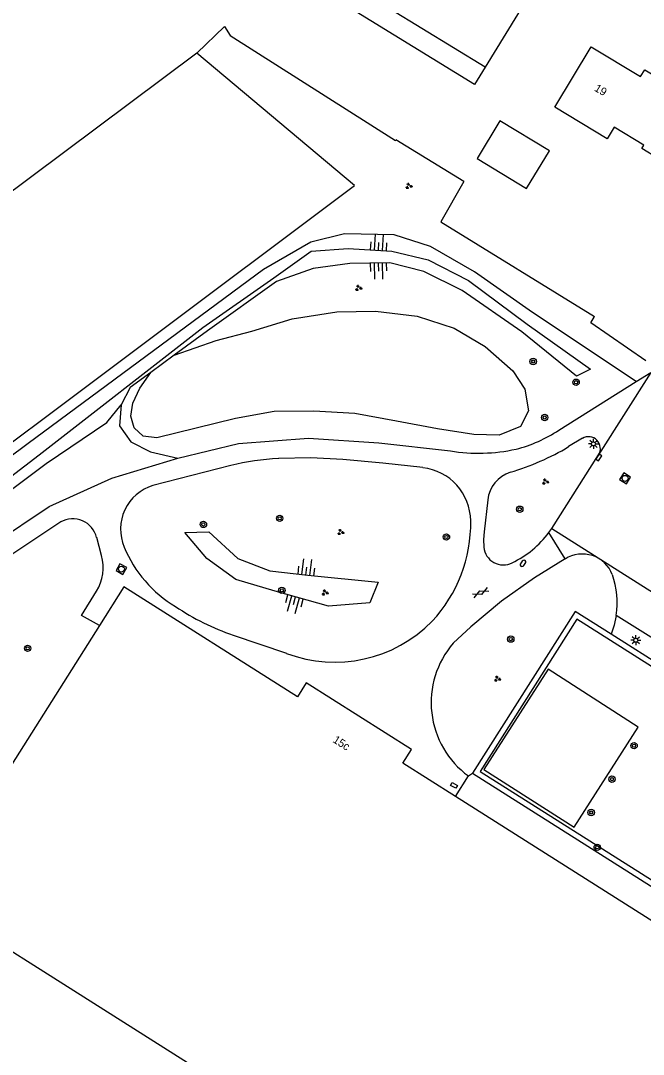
# Model space of a CAD drawing. Extents: x 136000 to 141000, y 400494 to 402006.
# Drawn here: x 138089.2 to 138167.1, y 401551.6 to 401680.8 of the extents above; entities that cross this region are included whole.
import ezdxf

# ---------------------------------------------------------------- set-up
doc = ezdxf.new("R2010")
doc.units = 0
for name, color, linetype in [('gg-afsc-draadraster', 7, 'Continuous'), ('gg-afsc-erfafscheiding', 7, 'Continuous'), ('gg-afsc-haag', 7, 'Continuous'), ('gg-afsc-hekwerk', 7, 'Continuous'), ('gg-anno-huisnummerreeks BGT', 7, 'Continuous'), ('gg-bbg-gedigitaliseerde bebouwing', 7, 'Continuous'), ('gg-bbg-gedigitaliseerde bijgebouw', 7, 'Continuous'), ('gg-bbg-hoofdgebouw', 7, 'Continuous'), ('gg-bbg-luifel en loopbrug', 7, 'Continuous'), ('gg-bbg-overig bouwwerk', 7, 'Continuous'), ('gg-knt-BGT kruinlijn', 7, 'Continuous'), ('gg-knt-bovenkant onderkant talud', 7, 'Continuous'), ('gg-knt-verharding', 7, 'Continuous'), ('gg-kntw-bovenkant insteek waterloop', 7, 'Continuous'), ('gt-grn-groengrens', 7, 'Continuous'), ('gt-grn-vlakafsluiter', 7, 'Continuous'), ('gt-symb-boom', 7, 'Continuous'), ('gt-symb-brandkraan', 7, 'Continuous'), ('gt-symb-gesloten verharding', 7, 'Continuous'), ('gt-symb-groenvak', 7, 'Continuous'), ('gt-symb-kolk', 7, 'Continuous'), ('gt-symb-kolk center center', 7, 'Continuous'), ('gt-symb-lichtmast', 7, 'Continuous'), ('gt-symb-rioolschacht', 7, 'Continuous'), ('gt-symb-talud symbool', 7, 'Continuous')]:
    doc.layers.add(name, color=color, linetype=linetype)

# ---------------------------------------------------------------- blocks, each defined once
blk = doc.blocks.new('gt0-BOOM')
at = {"layer": 'gt-symb-boom'}
for radius in [0.4, 0.2]:
    blk.add_circle((0, 0), radius, dxfattribs=at)
blk = doc.blocks.new('gt0-GRVAK')
at = {"layer": 'gt-symb-groenvak'}
for p, q in [((-0.11, 0.19), (-0.23, 0.24)), ((-0.18, 0.15), (0.09, 0.15)), ((-0.09, 0.21), (-0.16, 0.32)), ((-0.05, 0.21), (-0.05, 0.39)), ((0, 0.21), (0.06, 0.32)), ((0.02, 0.19), (0.13, 0.24)), ((0.26, -0.05), (0.2, 0.06)), ((0.3, -0.05), (0.3, 0.13)), ((0.35, -0.05), (0.41, 0.06)), ((-0.24, -0.23), (-0.36, -0.18)), ((-0.32, -0.26), (-0.05, -0.26)), ((-0.23, -0.21), (-0.29, -0.09)), ((-0.18, -0.2), (-0.18, -0.02)), ((-0.14, -0.21), (-0.07, -0.09)), ((-0.12, -0.23), (0, -0.18)), ((0.24, -0.07), (0.12, -0.02)), ((0.17, -0.11), (0.44, -0.11)), ((0.37, -0.07), (0.49, -0.02))]:
    blk.add_line(p, q, dxfattribs=at)
blk = doc.blocks.new('gt0-TALUD_1')
at = {"layer": 'gt-symb-talud symbool'}
for p, q in [((-1, -1), (-1, 0)), ((-0.5, -2), (-0.5, 0)), ((0, -1), (0, 0)), ((0.5, -2), (0.5, 0)), ((1, -1), (1, 0))]:
    blk.add_line(p, q, dxfattribs=at)
blk = doc.blocks.new('gt0-BR')
at = {"layer": 'gt-symb-brandkraan'}
for centre, radius, start, end in [((-0.24, 0), 0.206, 107.5669, 252.4331), ((0.6, -2.66), 3, 106.892, 107.5669), ((0, -0.69), 0.938, 73.108, 106.892), ((-0.6, -2.66), 3, 72.4331, 73.108), ((0.24, 0), 0.206, 287.567, 72.4331), ((0.6, 2.66), 3, 252.4331, 253.108), ((0, 0.69), 0.938, 253.108, 286.8921), ((-0.6, 2.66), 3, 286.8921, 287.567)]:
    blk.add_arc(centre, radius, start, end, dxfattribs=at)
blk = doc.blocks.new('gt0-LMAST')
at = {"layer": 'gt-symb-lichtmast'}
for p, q in [((-0.18, 0.17), (-0.45, 0.44)), ((-0.01, 0.25), (-0.01, 0.62)), ((0.17, 0.17), (0.44, 0.44)), ((-0.26, 0), (-0.63, 0)), ((-0.18, -0.18), (-0.45, -0.45)), ((-0.01, -0.25), (-0.01, -0.63)), ((0.44, -0.45), (0.17, -0.18)), ((0.24, 0), (0.62, 0))]:
    blk.add_line(p, q, dxfattribs=at)
blk.add_circle((-0.01, 0), 0.25, dxfattribs=at)
blk = doc.blocks.new('gt0-KOLK')
at = {"layer": 'gt-symb-kolk'}
blk.add_lwpolyline([(0, 0), (0.38, 0), (0.38, 0.4), (-0.38, 0.4), (-0.38, 0), (0, 0)], dxfattribs=at)
blk = doc.blocks.new('gt0-RS')
at = {"layer": 'gt-symb-rioolschacht'}
blk.add_lwpolyline([(-0.5, -0.5), (0.5, -0.5), (0.5, 0.5), (-0.5, 0.5)], close=True, dxfattribs=at)
blk.add_circle((0, 0), 0.375, dxfattribs=at)
blk = doc.blocks.new('gt0-GESVH1')
at = {"layer": 'gt-symb-gesloten verharding'}
for p, q in [((-0.99, -0.26), (0.01, 0.24)), ((0.01, -0.26), (-0.99, 0.24)), ((0.01, 0.24), (1.01, -0.26)), ((1.01, 0.24), (0.01, -0.26))]:
    blk.add_line(p, q, dxfattribs=at)
blk = doc.blocks.new('gt0-KOLKCC')
at = {"layer": 'gt-symb-kolk center center'}
blk.add_lwpolyline([(-0.37, 0.2), (0.38, 0.2), (0.38, -0.2), (-0.37, -0.2)], close=True, dxfattribs=at)

msp = doc.modelspace()

# ---------------------------------------------------------------- linework, layer by layer
at = {"layer": 'gg-afsc-draadraster'}
msp.add_line((138111.23, 401676.69), (138114.7, 401680.02), dxfattribs=at)
at = {"layer": 'gg-afsc-erfafscheiding'}
for p, q in [((138144.61, 401660.66), (138136.12, 401665.87)), ((138141.74, 401655.62), (138160.96, 401643.78))]:
    msp.add_line(p, q, dxfattribs=at)
at = {"layer": 'gg-afsc-haag'}
for p, q in [((138111.23, 401676.69), (138036.16, 401620.69)), ((138144.61, 401660.66), (138141.74, 401655.62))]:
    msp.add_line(p, q, dxfattribs=at)
at = {"layer": 'gg-afsc-hekwerk'}
for p, q in [((138158.52, 401606.93), (138145.68, 401586.75)), ((138163.01, 401604.1), (138158.52, 401606.93)), ((138189.93, 401587.05), (138163.01, 401604.1)), ((138145.68, 401586.75), (138183.77, 401562.65))]:
    msp.add_line(p, q, dxfattribs=at)
msp.add_lwpolyline([(138049.85, 401599.43), (138130.92, 401660.15), (138111.23, 401676.69)], dxfattribs=at)
at = {"layer": 'gg-bbg-gedigitaliseerde bebouwing'}
msp.add_line((138152.46, 401683.39), (138147.27, 401674.93), dxfattribs=at)
msp.add_lwpolyline([(138147.27, 401674.93), (138135.42, 401682.18), (138136.26, 401683.55), (138132.74, 401685.7)], dxfattribs=at)
at = {"layer": 'gg-bbg-gedigitaliseerde bijgebouw'}
msp.add_lwpolyline([(138149.11, 401668.25), (138146.26, 401663.54), (138152.46, 401659.79), (138155.31, 401664.5), (138149.11, 401668.25)], dxfattribs=at)
at = {"layer": 'gg-bbg-hoofdgebouw'}
for points in [[(138160.54, 401677.5), (138166.71, 401673.77), (138167.22, 401674.63), (138171.55, 401672.01), (138169.98, 401669.42), (138173.83, 401667.12), (138170.95, 401662.29), (138166.85, 401664.78), (138167.11, 401665.2), (138163.39, 401667.44), (138162.52, 401665.98), (138155.97, 401669.94), (138160.54, 401677.5)], [(138143.55, 401583.81), (138136.97, 401587.98), (138138.08, 401589.71), (138124.91, 401598.03), (138123.81, 401596.29), (138102.09, 401610.02), (138099.05, 401605.21)], [(138099.05, 401605.21), (138077.51, 401571.17), (138170.74, 401512.21), (138171.15, 401512.87), (138194.53, 401549.9), (138188.3, 401553.84)], [(138177.76, 401560.5), (138175.32, 401562.04), (138176.07, 401563.24), (138143.55, 401583.81)]]:
    msp.add_lwpolyline(points, dxfattribs=at)
at = {"layer": 'gg-bbg-luifel en loopbrug'}
msp.add_lwpolyline([(138147.27, 401674.93), (138145.95, 401672.78), (138130.59, 401682.2), (138132.74, 401685.7)], dxfattribs=at)
at = {"layer": 'gg-bbg-overig bouwwerk'}
msp.add_lwpolyline([(138166.41, 401592.5), (138155.15, 401599.72), (138147.13, 401587.2), (138158.4, 401579.99), (138166.41, 401592.5)], dxfattribs=at)
at = {"layer": 'gg-knt-BGT kruinlijn'}
for points in [[(138051.57, 401597.7), (138054.78, 401598.77), (138061.34, 401603.41), (138091.51, 401626.53), (138112, 401642.43), (138120.87, 401648.61), (138125.53, 401651.96), (138130.13, 401652.29), (138135.61, 401651.95), (138140.13, 401650.89), (138145.18, 401648.3), (138152.52, 401642.84), (138160.44, 401637.22), (138158.69, 401636.35), (138151.87, 401641.86), (138144.39, 401647.04), (138139.62, 401649.42), (138135.36, 401650.51), (138130.34, 401650.42), (138125.77, 401649.81), (138121.21, 401648.17), (138112.57, 401642), (138108.41, 401638.95)], [(138121.04, 401609.49), (138116.11, 401610.94), (138112.49, 401613.58), (138109.71, 401616.79), (138112.71, 401616.88), (138116.37, 401613.58), (138120.36, 401612.02), (138125.09, 401611.46), (138133.91, 401610.62), (138132.87, 401608.02), (138127.67, 401607.6), (138121.04, 401609.49)]]:
    msp.add_lwpolyline(points, dxfattribs=at)
at = {"layer": 'gg-knt-bovenkant onderkant talud'}
for points in [[(138166.17, 401635.66), (138153.2, 401644.29), (138145.96, 401649.36), (138140.46, 401652.54), (138135.88, 401653.98), (138129.68, 401654.11), (138125.48, 401653.1), (138119.55, 401649.66), (138090.14, 401627.91), (138051.04, 401598.83), (138051.57, 401597.7)], [(138105.49, 401636.81), (138102.91, 401634.92), (138101.77, 401632.74)], [(138051.57, 401597.7), (138052.57, 401595.58), (138054.76, 401595.96), (138058.77, 401597.89), (138063.17, 401601), (138070.27, 401606.72), (138083.85, 401619.06), (138092.4, 401625.44), (138099.96, 401630.54), (138101.77, 401632.74)], [(138101.77, 401632.74), (138101.55, 401630.15), (138103, 401628.14), (138105.43, 401626.89), (138108.84, 401626.08)]]:
    msp.add_lwpolyline(points, dxfattribs=at)
at = {"layer": 'gg-knt-verharding'}
for p, q in [((138167.97, 401636.79), (138161.46, 401626.5)), ((138166.17, 401635.66), (138167.97, 401636.79)), ((138156.49, 401629.6), (138166.17, 401635.66)), ((138159.43, 401628.58), (138157.71, 401627.54)), ((138155.61, 401617.33), (138161.46, 401626.5)), ((138115.47, 401625.18), (138105.74, 401622.68)), ((138155.25, 401616.82), (138155.61, 401617.33)), ((138157.26, 401613.5), (138155.25, 401616.82)), ((138099.32, 401613.93), (138098.71, 401616.2)), ((138191.2, 401589.06), (138163.65, 401606.45)), ((138115.78, 401603.99), (138122.44, 401601.72))]:
    msp.add_line(p, q, dxfattribs=at)
for points in [[(138108.84, 401626.08), (138116.44, 401627.94), (138125.19, 401628.61), (138133.97, 401628.01), (138142.93, 401627)], [(138073.08, 401603.91), (138079.49, 401609.97), (138085.76, 401615.4), (138092.75, 401620.05), (138100.62, 401623.6), (138108.84, 401626.08)], [(138139.48, 401624.91), (138134.49, 401625.47), (138129.49, 401625.93), (138125.48, 401626.15), (138121.46, 401626.06)], [(138147.59, 401620.88), (138147.14, 401616.88), (138147.07, 401615.93), (138147.11, 401614.98)], [(138094.21, 401618.13), (138087.6, 401613.72), (138081.19, 401608.24), (138074.62, 401602.07)], [(138155.61, 401617.33), (138233.11, 401568.28), (138244.06, 401585.61)], [(138157.26, 401613.5), (138153.45, 401611.15), (138149.33, 401608.24), (138145.49, 401605.01), (138143.28, 401602.97)], [(138099.05, 401605.21), (138096.81, 401606.46), (138098.68, 401609.49)], [(138163.65, 401606.45), (138163.4, 401605.25), (138163.01, 401604.1)], [(138189.93, 401587.05), (138189.56, 401586.46), (138158.74, 401605.97), (138146.65, 401586.97), (138184.14, 401563.24), (138183.77, 401562.65)]]:
    msp.add_lwpolyline(points, dxfattribs=at)
for centre, radius, start, end in [((138146.98, 401643.85), 17.14, 284.055, 303.7369), ((138160.19, 401627.29), 1.49, 327.9411, 120.7752), ((138146.44, 401648.71), 21.99, 260.8121, 282.3283), ((138141.75, 401654.11), 31, 286.2415, 300.9842), ((138123.19, 401593.44), 32.66, 93.035, 103.6593), ((138138.71, 401618.19), 6.76, 0.7328, 83.4817), ((138151.72, 401620.4), 4.15, 108.2073, 173.4461), ((138107.38, 401617.23), 5.69, 106.7287, 203.2009), ((138095.72, 401615.45), 3.07, 14.0367, 119.4708), ((138127.43, 401618.01), 18.05, 317.1087, 0.8444), ((138145.15, 401624.38), 12.62, 295.8986, 323.2027), ((138094.22, 401612.39), 5.32, 326.9426, 16.7646), ((138116.44, 401620.86), 15.45, 202.3444, 239.3986), ((138149.54, 401615.2), 2.44, 185.2054, 297.2263), ((138159.42, 401610.1), 4.02, 21.03, 122.4203), ((138153.26, 401608.03), 10.52, 351.3148, 19.4874), ((138125.39, 401632.4), 30, 235.906, 251.3081), ((138128.47, 401617.69), 17.08, 249.3079, 315.5065), ((138151.87, 401595.56), 11.35, 139.2175, 233.8845)]:
    msp.add_arc(centre, radius, start, end, dxfattribs=at)
at = {"layer": 'gg-kntw-bovenkant insteek waterloop'}
msp.add_line((138108.41, 401638.95), (138105.49, 401636.81), dxfattribs=at)
msp.add_lwpolyline([(138108.41, 401638.95), (138113.64, 401640.8), (138118.11, 401641.96), (138123.15, 401643.49), (138128.75, 401644.37), (138133.56, 401644.48), (138138.76, 401643.85), (138143.38, 401642.33), (138147.27, 401640.06), (138150.75, 401637), (138152.25, 401634.71), (138152.7, 401632.03), (138151.7, 401630.04), (138149.01, 401628.96), (138145.84, 401629.06), (138141.33, 401629.78), (138136.2, 401630.74), (138130.97, 401631.67), (138125.84, 401631.98), (138120.88, 401631.94), (138116.07, 401631.06), (138106.22, 401628.62), (138104.53, 401628.85), (138103.39, 401629.87), (138102.97, 401631.34), (138103.21, 401632.97), (138104.1, 401634.86), (138105.49, 401636.81)], dxfattribs=at)
at = {"layer": 'gt-grn-groengrens'}
for points in [[(138114.7, 401680.02), (138115.4, 401678.91), (138136.06, 401665.77), (138136.12, 401665.87)], [(138167.36, 401638.24), (138160.49, 401643.01), (138160.96, 401643.78)]]:
    msp.add_lwpolyline(points, dxfattribs=at)
at = {"layer": 'gt-grn-vlakafsluiter'}
for p, q in [((138145.18, 401586.39), (138145.68, 401586.75)), ((138143.55, 401583.81), (138145.18, 401586.39))]:
    msp.add_line(p, q, dxfattribs=at)

# ---------------------------------------------------------------- block references
at = {"layer": 'gt-symb-boom'}
for p in [(138153.28, 401638.17), (138158.64, 401635.58), (138154.72, 401631.18), (138121.59, 401618.58), (138151.6, 401619.72), (138112.05, 401617.82), (138142.43, 401616.25), (138121.86, 401609.58), (138150.48, 401603.49), (138090.08, 401602.34), (138165.89, 401590.18), (138163.13, 401585.99), (138160.53, 401581.83), (138161.29, 401577.47)]:
    msp.add_blockref('gt0-BOOM', p, dxfattribs=at)
at = {"layer": 'gt-symb-brandkraan', "rotation": 52.21490699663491}
msp.add_blockref('gt0-BR', (138152.01, 401612.96), dxfattribs=at)
at = {"layer": 'gt-symb-gesloten verharding', "rotation": 24.823140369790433}
msp.add_blockref('gt0-GESVH1', (138146.71, 401609.3), dxfattribs=at)
at = {"layer": 'gt-symb-groenvak'}
for p in [(138137.73, 401660.09), (138131.44, 401647.36), (138154.8, 401623.15), (138129.2, 401616.85), (138127.24, 401609.3), (138148.79, 401598.52)]:
    msp.add_blockref('gt0-GRVAK', p, dxfattribs=at)
at = {"layer": 'gt-symb-kolk', "rotation": -122.50151963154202}
msp.add_blockref('gt0-KOLK', (138161.32, 401626.29), dxfattribs=at)
at = {"layer": 'gt-symb-kolk center center', "rotation": 151.87577381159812}
msp.add_blockref('gt0-KOLKCC', (138143.39, 401585.2), dxfattribs=at)
at = {"layer": 'gt-symb-lichtmast'}
for p in [(138160.82, 401627.88), (138166.12, 401603.35)]:
    msp.add_blockref('gt0-LMAST', p, dxfattribs=at)
at = {"layer": 'gt-symb-rioolschacht'}
for p, rotation in [((138164.77, 401623.57), -32.33937707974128), ((138101.81, 401612.23), 150.34420224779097)]:
    msp.add_blockref('gt0-RS', p, dxfattribs=dict(at, rotation=rotation))
at = {"layer": 'gt-symb-talud symbool'}
for p, xscale, yscale, rotation in [((138133.89, 401652.06), 1.0004518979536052, 1.0004518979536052, 175.98782884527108), ((138133.95, 401650.46), 1.0003379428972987, 1.000337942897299, 1.489354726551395), ((138124.83, 401611.49), 0.9996369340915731, 0.999636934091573, 173.39396584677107), ((138123.58, 401608.77), 0.9997139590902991, 0.9997139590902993, -15.787947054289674)]:
    msp.add_blockref('gt0-TALUD_1', p, dxfattribs=dict(at, xscale=xscale, yscale=yscale, rotation=rotation))

# ---------------------------------------------------------------- texts
at = {"layer": 'gg-anno-huisnummerreeks BGT'}
for s, rotation, p in [('19', 328.9, (138160.83, 401672.06)), ('15c', 327.7, (138128.14, 401590.67))]:
    msp.add_text(s, height=1, rotation=rotation, dxfattribs=at).set_placement(p)

doc.saveas('drawing.dxf')
